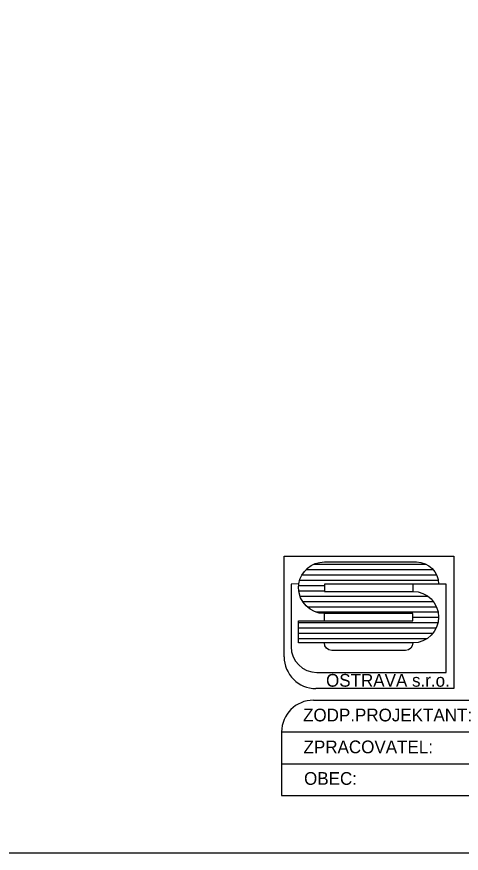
# Model space of a CAD drawing. Extents: x -557942 to -541772, y -1047288 to -1036007.
# Drawn here: x -551373 to -550953, y -1042803 to -1042014 of the extents above; entities that cross this region are included whole.
import ezdxf

# ---------------------------------------------------------------- set-up
doc = ezdxf.new("R2010")
doc.units = 0
doc.layers.add('Vrstva 1', color=7, linetype='Continuous')

msp = doc.modelspace()

# ---------------------------------------------------------------- linework, layer by layer
at = {"layer": 'Vrstva 1'}
for p, q in [((-551099.71, -1042535.45), (-550979.99, -1042535.45)), ((-551099.71, -1042535.45), (-550979.99, -1042535.45)), ((-551092.39, -1042530.45), (-550986.47, -1042530.45)), ((-551092.39, -1042530.45), (-550986.47, -1042530.45)), ((-551103.73, -1042540.45), (-550976.68, -1042540.45)), ((-551103.73, -1042540.45), (-550976.68, -1042540.45)), ((-551106.8, -1042550.45), (-551082.55, -1042550.45)), ((-551106.8, -1042550.45), (-551082.55, -1042550.45)), ((-551105.92, -1042545.45), (-550975.11, -1042545.45)), ((-551105.92, -1042545.45), (-550975.11, -1042545.45)), ((-551106.57, -1042555.45), (-551082.55, -1042555.45)), ((-551106.57, -1042555.45), (-551082.55, -1042555.45)), ((-551105.44, -1042560.45), (-550985.09, -1042560.45)), ((-551105.44, -1042560.45), (-550985.09, -1042560.45)), ((-551103.04, -1042565.45), (-550979.93, -1042565.45)), ((-551103.04, -1042565.45), (-550979.93, -1042565.45)), ((-551098.84, -1042570.45), (-550976.92, -1042570.45)), ((-551098.84, -1042570.45), (-550976.92, -1042570.45)), ((-551090.51, -1042575.45), (-550975.27, -1042575.45)), ((-551090.51, -1042575.45), (-550975.27, -1042575.45)), ((-550999.08, -1042580.45), (-550974.8, -1042580.45)), ((-550999.08, -1042580.45), (-550974.8, -1042580.45)), ((-551106.85, -1042585.45), (-550975.35, -1042585.45)), ((-551106.85, -1042585.45), (-550975.35, -1042585.45)), ((-551106.85, -1042590.45), (-550977.06, -1042590.45)), ((-551106.85, -1042590.45), (-550977.06, -1042590.45)), ((-551106.85, -1042595.45), (-550980.18, -1042595.45)), ((-551106.85, -1042595.45), (-550980.18, -1042595.45)), ((-551106.85, -1042600.45), (-550985.4, -1042600.45)), ((-551106.85, -1042600.45), (-550985.4, -1042600.45)), ((-551092.86, -1042658.67), (-550242.86, -1042658.67)), ((-551092.86, -1042658.67), (-550242.86, -1042658.67)), ((-551122.86, -1042688.67), (-550242.86, -1042688.67)), ((-551122.86, -1042688.67), (-551122.86, -1042748.67)), ((-551122.86, -1042688.67), (-550242.86, -1042688.67)), ((-551122.86, -1042688.67), (-551122.86, -1042748.67)), ((-551122.86, -1042718.67), (-550242.86, -1042718.67)), ((-551122.86, -1042718.67), (-550242.86, -1042718.67)), ((-551122.86, -1042748.67), (-550242.86, -1042748.67)), ((-551122.86, -1042748.67), (-550242.86, -1042748.67))]:
    msp.add_line(p, q, dxfattribs=at)
msp.add_lwpolyline([(-550122.86, -1039561.93), (-550122.86, -1042803.07), (-552622.86, -1042803.07), (-552622.86, -1039561.93)], close=True, dxfattribs=at)
for points in [[(-551120.48, -1042617.77), (-551120.48, -1042522.77), (-550960.48, -1042522.77), (-550960.48, -1042647.77), (-551090.48, -1042647.77)], [(-551120.48, -1042617.77), (-551120.48, -1042522.77), (-550960.48, -1042522.77), (-550960.48, -1042647.77), (-551090.48, -1042647.77)], [(-550999.08, -1042549.17), (-551082.55, -1042549.17), (-551082.55, -1042556.02), (-550999.08, -1042556.02), (-550994.13, -1042556.5), (-550989.55, -1042557.93), (-550985.36, -1042560.22), (-550981.84, -1042563.17), (-550978.88, -1042566.7), (-550976.69, -1042570.89), (-550975.26, -1042575.46), (-550974.78, -1042580.32), (-550975.26, -1042585.18), (-550976.69, -1042589.76), (-550978.88, -1042593.85), (-550981.84, -1042597.47), (-550985.36, -1042600.43), (-550989.55, -1042602.72), (-550994.13, -1042604.14), (-550999.08, -1042604.62), (-551082.55, -1042604.62), (-551106.85, -1042604.62), (-551106.85, -1042583.85), (-551082.55, -1042583.85), (-550999.08, -1042583.85), (-550999.08, -1042576.89), (-551082.55, -1042576.89), (-551087.41, -1042576.42), (-551091.99, -1042574.99), (-551096.08, -1042572.7), (-551099.71, -1042569.75), (-551102.66, -1042566.13), (-551104.95, -1042562.03), (-551106.38, -1042557.45), (-551106.85, -1042552.59), (-551106.76, -1042548.97), (-551105.71, -1042544.59), (-551103.9, -1042540.68), (-551101.42, -1042537.16), (-551098.47, -1042534.2), (-551094.94, -1042531.73), (-551091.13, -1042529.82), (-551086.94, -1042528.68), (-551082.55, -1042528.3), (-550995.65, -1042528.3), (-550991.37, -1042528.68), (-550987.46, -1042529.92), (-550983.93, -1042531.82), (-550980.88, -1042534.39), (-550978.31, -1042537.44), (-550976.4, -1042540.97), (-550975.17, -1042544.88), (-550974.78, -1042549.17), (-550999.08, -1042549.17)], [(-550999.08, -1042549.17), (-551082.55, -1042549.17), (-551082.55, -1042556.02), (-550999.08, -1042556.02), (-550994.13, -1042556.5), (-550989.55, -1042557.93), (-550985.36, -1042560.22), (-550981.84, -1042563.17), (-550978.88, -1042566.7), (-550976.69, -1042570.89), (-550975.26, -1042575.46), (-550974.78, -1042580.32), (-550975.26, -1042585.18), (-550976.69, -1042589.76), (-550978.88, -1042593.85), (-550981.84, -1042597.47), (-550985.36, -1042600.43), (-550989.55, -1042602.72), (-550994.13, -1042604.14), (-550999.08, -1042604.62), (-551082.55, -1042604.62), (-551106.85, -1042604.62), (-551106.85, -1042583.85), (-551082.55, -1042583.85), (-550999.08, -1042583.85), (-550999.08, -1042576.89), (-551082.55, -1042576.89), (-551087.41, -1042576.42), (-551091.99, -1042574.99), (-551096.08, -1042572.7), (-551099.71, -1042569.75), (-551102.66, -1042566.13), (-551104.95, -1042562.03), (-551106.38, -1042557.45), (-551106.85, -1042552.59), (-551106.76, -1042548.97), (-551105.71, -1042544.59), (-551103.9, -1042540.68), (-551101.42, -1042537.16), (-551098.47, -1042534.2), (-551094.94, -1042531.73), (-551091.13, -1042529.82), (-551086.94, -1042528.68), (-551082.55, -1042528.3), (-550995.65, -1042528.3), (-550991.37, -1042528.68), (-550987.46, -1042529.92), (-550983.93, -1042531.82), (-550980.88, -1042534.39), (-550978.31, -1042537.44), (-550976.4, -1042540.97), (-550975.17, -1042544.88), (-550974.78, -1042549.17), (-550999.08, -1042549.17)], [(-550967.73, -1042632.54), (-550967.73, -1042549.07), (-550974.78, -1042549.07), (-550999.08, -1042549.07), (-550999.08, -1042556.02), (-550994.13, -1042556.5), (-550989.55, -1042557.93), (-550985.36, -1042560.22), (-550981.84, -1042563.17), (-550978.88, -1042566.7), (-550976.69, -1042570.89), (-550975.26, -1042575.46), (-550974.78, -1042580.32), (-550975.26, -1042585.18), (-550976.69, -1042589.76), (-550978.88, -1042593.85), (-550981.84, -1042597.47), (-550985.36, -1042600.43), (-550989.55, -1042602.72), (-550994.13, -1042604.14), (-550999.08, -1042604.62), (-550999.65, -1042607.38), (-551001.09, -1042609.58), (-551003.28, -1042611.1), (-551005.95, -1042611.67), (-551075.6, -1042611.67), (-551078.36, -1042611.1), (-551080.56, -1042609.58), (-551081.98, -1042607.38), (-551082.55, -1042604.62), (-551106.85, -1042604.62), (-551106.85, -1042583.75), (-551082.55, -1042583.75), (-551082.55, -1042576.89), (-551087.41, -1042576.42), (-551091.99, -1042574.99), (-551096.08, -1042572.7), (-551099.71, -1042569.75), (-551102.66, -1042566.13), (-551104.95, -1042562.03), (-551106.38, -1042557.45), (-551106.85, -1042552.59), (-551106.76, -1042548.97), (-551113.9, -1042549.07), (-551113.9, -1042608.24), (-551113.43, -1042613.1), (-551112, -1042617.67), (-551109.71, -1042621.77), (-551106.76, -1042625.4), (-551103.14, -1042628.35), (-551099.04, -1042630.63), (-551094.46, -1042632.06), (-551089.61, -1042632.54), (-551089.42, -1042632.54), (-550967.73, -1042632.54)], [(-550967.73, -1042632.54), (-550967.73, -1042549.07), (-550974.78, -1042549.07), (-550999.08, -1042549.07), (-550999.08, -1042556.02), (-550994.13, -1042556.5), (-550989.55, -1042557.93), (-550985.36, -1042560.22), (-550981.84, -1042563.17), (-550978.88, -1042566.7), (-550976.69, -1042570.89), (-550975.26, -1042575.46), (-550974.78, -1042580.32), (-550975.26, -1042585.18), (-550976.69, -1042589.76), (-550978.88, -1042593.85), (-550981.84, -1042597.47), (-550985.36, -1042600.43), (-550989.55, -1042602.72), (-550994.13, -1042604.14), (-550999.08, -1042604.62), (-550999.65, -1042607.38), (-551001.09, -1042609.58), (-551003.28, -1042611.1), (-551005.95, -1042611.67), (-551075.6, -1042611.67), (-551078.36, -1042611.1), (-551080.56, -1042609.58), (-551081.98, -1042607.38), (-551082.55, -1042604.62), (-551106.85, -1042604.62), (-551106.85, -1042583.75), (-551082.55, -1042583.75), (-551082.55, -1042576.89), (-551087.41, -1042576.42), (-551091.99, -1042574.99), (-551096.08, -1042572.7), (-551099.71, -1042569.75), (-551102.66, -1042566.13), (-551104.95, -1042562.03), (-551106.38, -1042557.45), (-551106.85, -1042552.59), (-551106.76, -1042548.97), (-551113.9, -1042549.07), (-551113.9, -1042608.24), (-551113.43, -1042613.1), (-551112, -1042617.67), (-551109.71, -1042621.77), (-551106.76, -1042625.4), (-551103.14, -1042628.35), (-551099.04, -1042630.63), (-551094.46, -1042632.06), (-551089.61, -1042632.54), (-551089.42, -1042632.54), (-550967.73, -1042632.54)]]:
    msp.add_lwpolyline(points, dxfattribs=at)
for centre, start, end in [((-551090.48, -1042617.77), 180, 270), ((-551090.48, -1042617.77), 180, 270), ((-551092.86, -1042688.66), 90, 180), ((-551092.86, -1042688.66), 90, 180)]:
    msp.add_arc(centre, 30, start, end, dxfattribs=at)

# ---------------------------------------------------------------- texts
for s, p in [('OSTRAVA s.r.o.', (-551080.98, -1042645.94)), ('OSTRAVA s.r.o.', (-551080.98, -1042645.94)), ('ZODP.PROJEKTANT:', (-551102.66, -1042678.66)), ('ZPRACOVATEL:', (-551102.18, -1042708.73)), ('ZPRACOVATEL:', (-551102.18, -1042708.73)), ('OBEC:', (-551101.71, -1042738.5))]:
    msp.add_text(s, height=12, dxfattribs=at).set_placement(p)

doc.saveas('drawing.dxf')
